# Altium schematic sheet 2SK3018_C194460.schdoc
size 127 x 101 mm
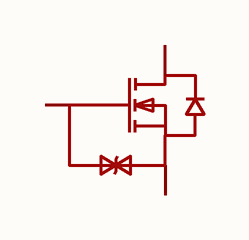
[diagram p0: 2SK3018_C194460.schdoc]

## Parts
Q?  2sk3018_c194460  [SOT-323-3_L2.0-W1.3-P1.30-LS2.1-BR]  (value not drawn)

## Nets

Not connected (* = marked no-connect by the designer): Q? 1(G) 2(S) 3(D)

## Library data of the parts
Q? = 2sk3018_c194460: 数量:1个N沟道;漏源电压(Vdss):30V;连续漏极电流(Id):100mA;导通电阻(RDS(on)):13Ω@2.5V;耗散功率(Pd):200mW;阈值电压(Vgs(th)):1.5V;; Manufacturer: CJ(江苏长电/长晶); AddInBom: yes; ModelId: 59529c0d6fc749f28f2d0659e12986b4; ModelName: SOT-323-3_L2.0-W1.3-H1.0-LS2.1-P1.30; ModelTransform: 78.74,82.677,0,90,0,0,0.0005,0,0; Number: 1个N沟道; Drain to Source Voltage: 30V; Current - Continuous Drain(Id): 100mA; Pd - Power Dissipation: 200mW; Gate Threshold Voltage (Vgs(th)): 1.5V; Input Capacitance(Ciss): 13pF; Reverse Transfer Capacitance (Crss@Vds): 4pF; Type: N沟道; Output Capacitance(Coss): 9pF; Vgs: ±20V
